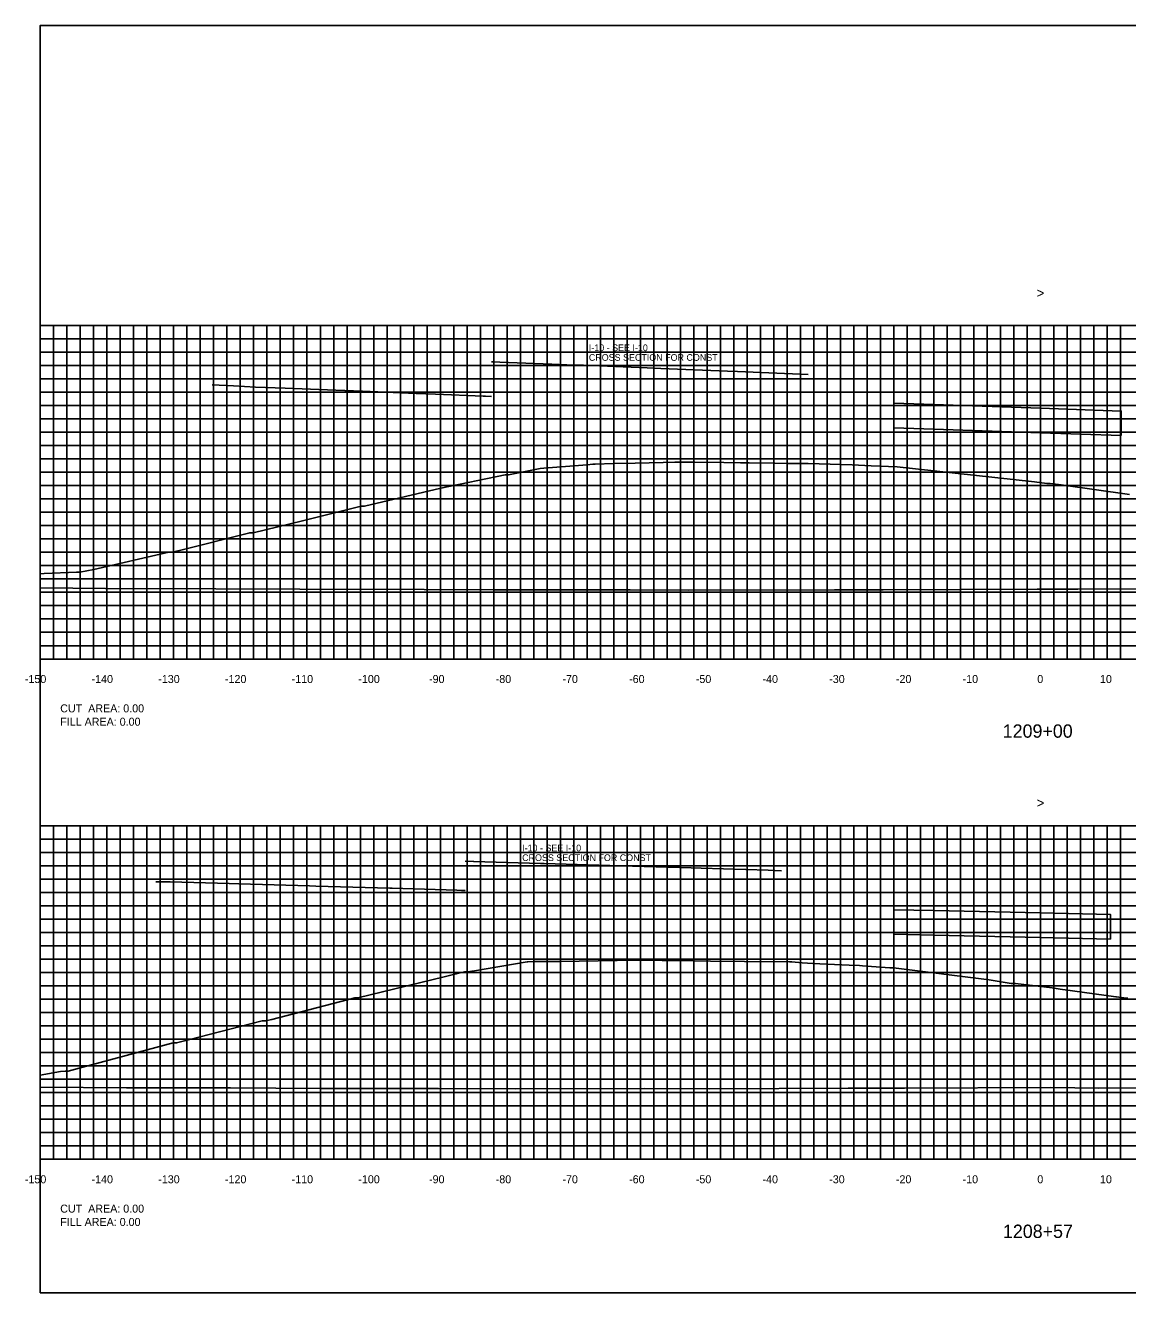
# Model space of a CAD drawing. Extents: x 1797305 to 1804485, y 245831 to 250849.
# Drawn here: x 1803498.8 to 1803664, y 250079.4 to 250269.4 of the extents above; entities that cross this region are included whole.
import ezdxf

# ---------------------------------------------------------------- set-up
doc = ezdxf.new("R2010")
doc.units = 0
for name, color, linetype in [('1', 7, 'Continuous'), ('10', 7, 'Continuous'), ('29', 7, 'Continuous'), ('CL-CNST', 7, 'Continuous'), ('EDPV-LINE', 7, 'Continuous'), ('Level 31', 7, 'Continuous'), ('LIMT-CSLINE', 7, 'Continuous'), ('M-ROADS', 7, 'Continuous'), ('SURVEY - DRAINAGE - Area Shapes', 7, 'Continuous')]:
    doc.layers.add(name, color=color, linetype=linetype)

msp = doc.modelspace()

# ---------------------------------------------------------------- linework, layer by layer
msp.add_lwpolyline([(1803501, 250079.43), (1803801, 250079.43), (1803801, 250269.43), (1803501, 250269.43)], close=True)
at = {"layer": '29'}
for p, q in [((1803501, 250224.43), (1803801, 250224.43)), ((1803501, 250174.43), (1803501, 250224.43)), ((1803503, 250174.43), (1803503, 250224.43)), ((1803505, 250174.43), (1803505, 250224.43)), ((1803507, 250174.43), (1803507, 250224.43)), ((1803509, 250174.43), (1803509, 250224.43)), ((1803511, 250174.43), (1803511, 250224.43)), ((1803513, 250174.43), (1803513, 250224.43)), ((1803515, 250174.43), (1803515, 250224.43)), ((1803517, 250174.43), (1803517, 250224.43)), ((1803519, 250174.43), (1803519, 250224.43)), ((1803521, 250174.43), (1803521, 250224.43)), ((1803523, 250174.43), (1803523, 250224.43)), ((1803525, 250174.43), (1803525, 250224.43)), ((1803527, 250174.43), (1803527, 250224.43)), ((1803529, 250174.43), (1803529, 250224.43)), ((1803531, 250174.43), (1803531, 250224.43)), ((1803533, 250174.43), (1803533, 250224.43)), ((1803535, 250174.43), (1803535, 250224.43)), ((1803537, 250174.43), (1803537, 250224.43)), ((1803539, 250174.43), (1803539, 250224.43)), ((1803541, 250174.43), (1803541, 250224.43)), ((1803543, 250174.43), (1803543, 250224.43)), ((1803545, 250174.43), (1803545, 250224.43)), ((1803547, 250174.43), (1803547, 250224.43)), ((1803549, 250174.43), (1803549, 250224.43)), ((1803551, 250174.43), (1803551, 250224.43)), ((1803553, 250174.43), (1803553, 250224.43)), ((1803555, 250174.43), (1803555, 250224.43)), ((1803557, 250174.43), (1803557, 250224.43)), ((1803559, 250174.43), (1803559, 250224.43)), ((1803561, 250174.43), (1803561, 250224.43)), ((1803563, 250174.43), (1803563, 250224.43)), ((1803565, 250174.43), (1803565, 250224.43)), ((1803567, 250174.43), (1803567, 250224.43)), ((1803569, 250174.43), (1803569, 250224.43)), ((1803571, 250174.43), (1803571, 250224.43)), ((1803573, 250174.43), (1803573, 250224.43)), ((1803575, 250174.43), (1803575, 250224.43)), ((1803577, 250174.43), (1803577, 250224.43)), ((1803579, 250174.43), (1803579, 250224.43)), ((1803581, 250174.43), (1803581, 250224.43)), ((1803583, 250174.43), (1803583, 250224.43)), ((1803585, 250174.43), (1803585, 250224.43)), ((1803587, 250174.43), (1803587, 250224.43)), ((1803589, 250174.43), (1803589, 250224.43)), ((1803591, 250174.43), (1803591, 250224.43)), ((1803593, 250174.43), (1803593, 250224.43)), ((1803595, 250174.43), (1803595, 250224.43)), ((1803597, 250174.43), (1803597, 250224.43)), ((1803599, 250174.43), (1803599, 250224.43)), ((1803601, 250174.43), (1803601, 250224.43)), ((1803603, 250174.43), (1803603, 250224.43)), ((1803605, 250174.43), (1803605, 250224.43)), ((1803607, 250174.43), (1803607, 250224.43)), ((1803609, 250174.43), (1803609, 250224.43)), ((1803611, 250174.43), (1803611, 250224.43)), ((1803613, 250174.43), (1803613, 250224.43)), ((1803615, 250174.43), (1803615, 250224.43)), ((1803617, 250174.43), (1803617, 250224.43)), ((1803619, 250174.43), (1803619, 250224.43)), ((1803621, 250174.43), (1803621, 250224.43)), ((1803623, 250174.43), (1803623, 250224.43)), ((1803625, 250174.43), (1803625, 250224.43)), ((1803627, 250174.43), (1803627, 250224.43)), ((1803629, 250174.43), (1803629, 250224.43)), ((1803631, 250174.43), (1803631, 250224.43)), ((1803633, 250174.43), (1803633, 250224.43)), ((1803635, 250174.43), (1803635, 250224.43)), ((1803637, 250174.43), (1803637, 250224.43)), ((1803639, 250174.43), (1803639, 250224.43)), ((1803641, 250174.43), (1803641, 250224.43)), ((1803643, 250174.43), (1803643, 250224.43)), ((1803645, 250174.43), (1803645, 250224.43)), ((1803647, 250174.43), (1803647, 250224.43)), ((1803649, 250174.43), (1803649, 250224.43)), ((1803651, 250174.43), (1803651, 250224.43)), ((1803653, 250174.43), (1803653, 250224.43)), ((1803655, 250174.43), (1803655, 250224.43)), ((1803657, 250174.43), (1803657, 250224.43)), ((1803659, 250174.43), (1803659, 250224.43)), ((1803661, 250174.43), (1803661, 250224.43)), ((1803663, 250174.43), (1803663, 250224.43)), ((1803501, 250222.43), (1803801, 250222.43)), ((1803501, 250220.43), (1803801, 250220.43)), ((1803501, 250218.43), (1803801, 250218.43)), ((1803501, 250216.43), (1803801, 250216.43)), ((1803501, 250214.43), (1803801, 250214.43)), ((1803501, 250212.43), (1803801, 250212.43)), ((1803501, 250210.43), (1803801, 250210.43)), ((1803501, 250208.43), (1803801, 250208.43)), ((1803501, 250206.43), (1803801, 250206.43)), ((1803501, 250204.43), (1803801, 250204.43)), ((1803501, 250202.43), (1803801, 250202.43)), ((1803501, 250200.43), (1803801, 250200.43)), ((1803501, 250198.43), (1803801, 250198.43)), ((1803501, 250196.43), (1803801, 250196.43)), ((1803501, 250194.43), (1803801, 250194.43)), ((1803501, 250192.43), (1803801, 250192.43)), ((1803501, 250190.43), (1803801, 250190.43)), ((1803501, 250188.43), (1803801, 250188.43)), ((1803501, 250186.43), (1803801, 250186.43)), ((1803501, 250184.43), (1803801, 250184.43)), ((1803501, 250182.43), (1803801, 250182.43)), ((1803501, 250180.43), (1803801, 250180.43)), ((1803501, 250178.43), (1803801, 250178.43)), ((1803501, 250176.43), (1803801, 250176.43)), ((1803501, 250174.43), (1803801, 250174.43)), ((1803501, 250149.43), (1803801, 250149.43)), ((1803501, 250099.43), (1803501, 250149.43)), ((1803503, 250099.43), (1803503, 250149.43)), ((1803505, 250099.43), (1803505, 250149.43)), ((1803507, 250099.43), (1803507, 250149.43)), ((1803509, 250099.43), (1803509, 250149.43)), ((1803511, 250099.43), (1803511, 250149.43)), ((1803513, 250099.43), (1803513, 250149.43)), ((1803515, 250099.43), (1803515, 250149.43)), ((1803517, 250099.43), (1803517, 250149.43)), ((1803519, 250099.43), (1803519, 250149.43)), ((1803521, 250099.43), (1803521, 250149.43)), ((1803523, 250099.43), (1803523, 250149.43)), ((1803525, 250099.43), (1803525, 250149.43)), ((1803527, 250099.43), (1803527, 250149.43)), ((1803529, 250099.43), (1803529, 250149.43)), ((1803531, 250099.43), (1803531, 250149.43)), ((1803533, 250099.43), (1803533, 250149.43)), ((1803535, 250099.43), (1803535, 250149.43)), ((1803537, 250099.43), (1803537, 250149.43)), ((1803539, 250099.43), (1803539, 250149.43)), ((1803541, 250099.43), (1803541, 250149.43)), ((1803543, 250099.43), (1803543, 250149.43)), ((1803545, 250099.43), (1803545, 250149.43)), ((1803547, 250099.43), (1803547, 250149.43)), ((1803549, 250099.43), (1803549, 250149.43)), ((1803551, 250099.43), (1803551, 250149.43)), ((1803553, 250099.43), (1803553, 250149.43)), ((1803555, 250099.43), (1803555, 250149.43)), ((1803557, 250099.43), (1803557, 250149.43)), ((1803559, 250099.43), (1803559, 250149.43)), ((1803561, 250099.43), (1803561, 250149.43)), ((1803563, 250099.43), (1803563, 250149.43)), ((1803565, 250099.43), (1803565, 250149.43)), ((1803567, 250099.43), (1803567, 250149.43)), ((1803569, 250099.43), (1803569, 250149.43)), ((1803571, 250099.43), (1803571, 250149.43)), ((1803573, 250099.43), (1803573, 250149.43)), ((1803575, 250099.43), (1803575, 250149.43)), ((1803577, 250099.43), (1803577, 250149.43)), ((1803579, 250099.43), (1803579, 250149.43)), ((1803581, 250099.43), (1803581, 250149.43)), ((1803583, 250099.43), (1803583, 250149.43)), ((1803585, 250099.43), (1803585, 250149.43)), ((1803587, 250099.43), (1803587, 250149.43)), ((1803589, 250099.43), (1803589, 250149.43)), ((1803591, 250099.43), (1803591, 250149.43)), ((1803593, 250099.43), (1803593, 250149.43)), ((1803595, 250099.43), (1803595, 250149.43)), ((1803597, 250099.43), (1803597, 250149.43)), ((1803599, 250099.43), (1803599, 250149.43)), ((1803601, 250099.43), (1803601, 250149.43)), ((1803603, 250099.43), (1803603, 250149.43)), ((1803605, 250099.43), (1803605, 250149.43)), ((1803607, 250099.43), (1803607, 250149.43)), ((1803609, 250099.43), (1803609, 250149.43)), ((1803611, 250099.43), (1803611, 250149.43)), ((1803613, 250099.43), (1803613, 250149.43)), ((1803615, 250099.43), (1803615, 250149.43)), ((1803617, 250099.43), (1803617, 250149.43)), ((1803619, 250099.43), (1803619, 250149.43)), ((1803621, 250099.43), (1803621, 250149.43)), ((1803623, 250099.43), (1803623, 250149.43)), ((1803625, 250099.43), (1803625, 250149.43)), ((1803627, 250099.43), (1803627, 250149.43)), ((1803629, 250099.43), (1803629, 250149.43)), ((1803631, 250099.43), (1803631, 250149.43)), ((1803633, 250099.43), (1803633, 250149.43)), ((1803635, 250099.43), (1803635, 250149.43)), ((1803637, 250099.43), (1803637, 250149.43)), ((1803639, 250099.43), (1803639, 250149.43)), ((1803641, 250099.43), (1803641, 250149.43)), ((1803643, 250099.43), (1803643, 250149.43)), ((1803645, 250099.43), (1803645, 250149.43)), ((1803647, 250099.43), (1803647, 250149.43)), ((1803649, 250099.43), (1803649, 250149.43)), ((1803651, 250099.43), (1803651, 250149.43)), ((1803653, 250099.43), (1803653, 250149.43)), ((1803655, 250099.43), (1803655, 250149.43)), ((1803657, 250099.43), (1803657, 250149.43)), ((1803659, 250099.43), (1803659, 250149.43)), ((1803661, 250099.43), (1803661, 250149.43)), ((1803663, 250099.43), (1803663, 250149.43)), ((1803501, 250147.43), (1803801, 250147.43)), ((1803501, 250145.43), (1803801, 250145.43)), ((1803501, 250143.43), (1803801, 250143.43)), ((1803501, 250141.43), (1803801, 250141.43)), ((1803501, 250139.43), (1803801, 250139.43)), ((1803501, 250137.43), (1803801, 250137.43)), ((1803501, 250135.43), (1803801, 250135.43)), ((1803501, 250133.43), (1803801, 250133.43)), ((1803501, 250131.43), (1803801, 250131.43)), ((1803501, 250129.43), (1803801, 250129.43)), ((1803501, 250127.43), (1803801, 250127.43)), ((1803501, 250125.43), (1803801, 250125.43)), ((1803501, 250123.43), (1803801, 250123.43)), ((1803501, 250121.43), (1803801, 250121.43)), ((1803501, 250119.43), (1803801, 250119.43)), ((1803501, 250117.43), (1803801, 250117.43)), ((1803501, 250115.43), (1803801, 250115.43)), ((1803501, 250113.43), (1803801, 250113.43)), ((1803501, 250111.43), (1803801, 250111.43)), ((1803501, 250109.43), (1803801, 250109.43)), ((1803501, 250107.43), (1803801, 250107.43)), ((1803501, 250105.43), (1803801, 250105.43)), ((1803501, 250103.43), (1803801, 250103.43)), ((1803501, 250101.43), (1803801, 250101.43)), ((1803501, 250099.43), (1803801, 250099.43))]:
    msp.add_line(p, q, dxfattribs=at)
at = {"layer": 'CL-CNST'}
for points in [[(1803568.67, 250219), (1803568.99, 250218.99), (1803569.93, 250218.95), (1803577.69, 250218.63), (1803579.97, 250218.55), (1803582.48, 250218.46), (1803592.02, 250218.07), (1803594.03, 250217.99), (1803604.07, 250217.57), (1803605.57, 250217.52), (1803616.12, 250217.08)], [(1803526.77, 250215.52), (1803530, 250215.39), (1803533.27, 250215.21), (1803537.75, 250215.05), (1803545.32, 250214.73), (1803549.3, 250214.59), (1803557.37, 250214.24), (1803560.28, 250214.14), (1803567.41, 250213.83), (1803567.74, 250213.82), (1803568.67, 250213.78)], [(1803629, 250212.79), (1803635, 250212.58), (1803651, 250212.03), (1803663.1, 250211.61)], [(1803501, 250185.09), (1803510.77, 250185), (1803527.31, 250184.97), (1803539.92, 250184.88), (1803558.56, 250184.87), (1803569.08, 250184.79), (1803589.45, 250184.81), (1803598.24, 250184.75), (1803620.07, 250184.81), (1803627.4, 250184.78), (1803650.47, 250184.88), (1803656.56, 250184.88), (1803680.69, 250185), (1803685.72, 250184.91), (1803710.78, 250185.05), (1803714.88, 250185.09), (1803718.62, 250185.06), (1803744.03, 250185.2), (1803747.27, 250185.25), (1803773.19, 250185.39), (1803775.9, 250185.32), (1803801, 250185.47)], [(1803564.71, 250144.11), (1803565.95, 250144.07), (1803565.96, 250144.07), (1803566.03, 250144.07), (1803576, 250143.78), (1803576.55, 250143.76), (1803588.05, 250143.42), (1803598.59, 250143.11), (1803600.1, 250143.05), (1803610.14, 250142.75), (1803612.16, 250142.68)], [(1803518.36, 250141.03), (1803520.46, 250141.01), (1803529.31, 250140.77), (1803530.78, 250140.74), (1803541.36, 250140.42), (1803542.32, 250140.39), (1803553.41, 250140.06), (1803553.79, 250140.05), (1803563.45, 250139.75), (1803563.46, 250139.75), (1803564.17, 250139.73), (1803564.7, 250139.71), (1803564.7, 250139.71)], [(1803629, 250136.85), (1803635, 250136.72), (1803651, 250136.37), (1803661.47, 250136.13)], [(1803501, 250110.24), (1803513.94, 250110.15), (1803529.55, 250110.14), (1803543.1, 250110.05), (1803560.71, 250110.06), (1803572.25, 250109.98), (1803591.54, 250110.03), (1803601.41, 250110), (1803622.13, 250110.08), (1803630.57, 250110.09), (1803652.52, 250110.19), (1803659.73, 250110.07), (1803682.75, 250110.19), (1803688.89, 250110.26), (1803694.5, 250110.22), (1803718.05, 250110.35), (1803723.18, 250110.43), (1803747.21, 250110.56), (1803751.83, 250110.43), (1803776.36, 250110.58), (1803782.45, 250110.38), (1803801, 250110.51)]]:
    msp.add_lwpolyline(points, dxfattribs=at)
at = {"layer": 'Level 31'}
for p, q in [((1803500.94, 250224.43), (1803501, 250224.43)), ((1803501, 250174.43), (1803501, 250224.43)), ((1803500.94, 250214.43), (1803501, 250214.43)), ((1803500.94, 250204.43), (1803501, 250204.43)), ((1803500.94, 250194.43), (1803501, 250194.43)), ((1803500.94, 250184.43), (1803501, 250184.43)), ((1803500.94, 250174.43), (1803501, 250174.43)), ((1803501, 250174.43), (1803801, 250174.43)), ((1803501, 250174.37), (1803501, 250174.43)), ((1803511, 250174.37), (1803511, 250174.43)), ((1803521, 250174.37), (1803521, 250174.43)), ((1803531, 250174.37), (1803531, 250174.43)), ((1803541, 250174.37), (1803541, 250174.43)), ((1803551, 250174.37), (1803551, 250174.43)), ((1803561, 250174.37), (1803561, 250174.43)), ((1803571, 250174.37), (1803571, 250174.43)), ((1803581, 250174.37), (1803581, 250174.43)), ((1803591, 250174.37), (1803591, 250174.43)), ((1803601, 250174.37), (1803601, 250174.43)), ((1803611, 250174.37), (1803611, 250174.43)), ((1803621, 250174.37), (1803621, 250174.43)), ((1803631, 250174.37), (1803631, 250174.43)), ((1803641, 250174.37), (1803641, 250174.43)), ((1803651, 250174.37), (1803651, 250174.43)), ((1803661, 250174.37), (1803661, 250174.43)), ((1803500.94, 250149.43), (1803501, 250149.43)), ((1803501, 250099.43), (1803501, 250149.43)), ((1803500.94, 250139.43), (1803501, 250139.43)), ((1803500.94, 250129.43), (1803501, 250129.43)), ((1803500.94, 250119.43), (1803501, 250119.43)), ((1803500.94, 250109.43), (1803501, 250109.43)), ((1803500.94, 250099.43), (1803501, 250099.43)), ((1803501, 250099.43), (1803801, 250099.43)), ((1803501, 250099.37), (1803501, 250099.43)), ((1803511, 250099.37), (1803511, 250099.43)), ((1803521, 250099.37), (1803521, 250099.43)), ((1803531, 250099.37), (1803531, 250099.43)), ((1803541, 250099.37), (1803541, 250099.43)), ((1803551, 250099.37), (1803551, 250099.43)), ((1803561, 250099.37), (1803561, 250099.43)), ((1803571, 250099.37), (1803571, 250099.43)), ((1803581, 250099.37), (1803581, 250099.43)), ((1803591, 250099.37), (1803591, 250099.43)), ((1803601, 250099.37), (1803601, 250099.43)), ((1803611, 250099.37), (1803611, 250099.43)), ((1803621, 250099.37), (1803621, 250099.43)), ((1803631, 250099.37), (1803631, 250099.43)), ((1803641, 250099.37), (1803641, 250099.43)), ((1803651, 250099.37), (1803651, 250099.43)), ((1803661, 250099.37), (1803661, 250099.43))]:
    msp.add_line(p, q, dxfattribs=at)
at = {"layer": 'M-ROADS'}
for points in [[(1803501, 250187.22), (1803501.58, 250187.26), (1803506.46, 250187.44), (1803506.86, 250187.44), (1803506.93, 250187.45), (1803509.03, 250187.87), (1803520.28, 250190.43), (1803520.29, 250190.43), (1803520.78, 250190.43), (1803521.61, 250190.64), (1803521.66, 250190.66), (1803532.41, 250193.37), (1803532.64, 250193.37), (1803532.92, 250193.37), (1803540.35, 250195.17), (1803549.11, 250197.35), (1803549.4, 250197.35), (1803549.63, 250197.35), (1803561.05, 250200.04), (1803570.7, 250202.02), (1803570.91, 250202.02), (1803571.21, 250202.02), (1803575.96, 250202.98), (1803576.52, 250203.06), (1803583, 250203.56), (1803583.88, 250203.65), (1803584.19, 250203.66), (1803586.97, 250203.73), (1803590.22, 250203.81), (1803594.38, 250203.91), (1803596.16, 250203.96), (1803599.16, 250203.93), (1803603.49, 250203.89), (1803605.99, 250203.86), (1803607.29, 250203.85), (1803611.14, 250203.79), (1803612.96, 250203.76), (1803613.41, 250203.76), (1803614.68, 250203.75), (1803615.5, 250203.74), (1803615.65, 250203.74), (1803616.16, 250203.72), (1803622.76, 250203.56), (1803625.59, 250203.39), (1803629.5, 250203.24), (1803650.06, 250200.97), (1803651.93, 250200.75), (1803651.99, 250200.75), (1803652.44, 250200.75), (1803654.08, 250200.52), (1803664.32, 250199.09)], [(1803501, 250112.04), (1803504.05, 250112.57), (1803504.75, 250112.63), (1803505.18, 250112.63), (1803507.39, 250113.23), (1803520.93, 250116.87), (1803520.99, 250116.87), (1803521.45, 250116.87), (1803523.24, 250117.34), (1803534.28, 250120.17), (1803534.3, 250120.17), (1803534.78, 250120.17), (1803535.74, 250120.4), (1803548.15, 250123.61), (1803548.51, 250123.61), (1803548.64, 250123.61), (1803561.57, 250126.79), (1803563.39, 250127.22), (1803564.61, 250127.51), (1803564.62, 250127.51), (1803565.09, 250127.51), (1803565.73, 250127.61), (1803565.84, 250127.62), (1803574, 250129.01), (1803574.11, 250129.01), (1803574.95, 250129.06), (1803575.02, 250129.06), (1803575.51, 250129.06), (1803575.7, 250129.06), (1803578.56, 250129.06), (1803578.94, 250129.06), (1803578.96, 250129.07), (1803590.34, 250129.3), (1803591.69, 250129.28), (1803594.25, 250129.25), (1803599.02, 250129.19), (1803601.52, 250129.15), (1803606.6, 250129.1), (1803613.33, 250129.03), (1803613.33, 250129.03), (1803613.69, 250129.01), (1803615.24, 250128.9), (1803616.86, 250128.79), (1803617.87, 250128.74), (1803622.28, 250128.53), (1803623.85, 250128.46), (1803624.31, 250128.43), (1803628.41, 250128.15), (1803628.83, 250128.15), (1803628.92, 250128.15), (1803643.26, 250126.33), (1803646.57, 250125.79), (1803646.66, 250125.78), (1803647.07, 250125.78), (1803647.23, 250125.76), (1803652.73, 250125.11), (1803653.93, 250124.94), (1803655.78, 250124.69), (1803659.02, 250124.24), (1803662.3, 250123.77), (1803662.37, 250123.76), (1803663.47, 250123.62), (1803663.89, 250123.58), (1803664, 250123.56), (1803664.08, 250123.56)]]:
    msp.add_lwpolyline(points, dxfattribs=at)
at = {"layer": 'SURVEY - DRAINAGE - Area Shapes'}
for points in [[(1803663.1, 250207.93), (1803663.1, 250211.61), (1803651, 250212.03), (1803635, 250212.58), (1803629, 250212.79), (1803629, 250209.11), (1803635, 250208.9), (1803651, 250208.35)], [(1803661.47, 250132.45), (1803661.47, 250136.13), (1803651, 250136.37), (1803635, 250136.72), (1803629, 250136.85), (1803629, 250133.17), (1803635, 250133.04), (1803651, 250132.69)]]:
    msp.add_lwpolyline(points, close=True, dxfattribs=at)

# ---------------------------------------------------------------- texts
at = {"layer": '1'}
for s, p in [('1209+00', (1803645.32, 250162.63)), ('1208+57', (1803645.35, 250087.63))]:
    msp.add_text(s, height=2, dxfattribs=at).set_placement(p)
at = {"layer": '10'}
for s, p in [('-150', (1803498.7, 250170.83)), ('-140', (1803508.7, 250170.83)), ('-130', (1803518.7, 250170.83)), ('-120', (1803528.7, 250170.83)), ('-110', (1803538.7, 250170.83)), ('-100', (1803548.7, 250170.83)), ('-90', (1803559.3, 250170.83)), ('-80', (1803569.3, 250170.83)), ('-70', (1803579.3, 250170.83)), ('-60', (1803589.3, 250170.83)), ('-50', (1803599.3, 250170.83)), ('-40', (1803609.3, 250170.83)), ('-30', (1803619.3, 250170.83)), ('-20', (1803629.3, 250170.83)), ('-10', (1803639.3, 250170.83)), ('0', (1803650.5, 250170.83)), ('10', (1803659.9, 250170.83)), ('-150', (1803498.7, 250095.83)), ('-140', (1803508.7, 250095.83)), ('-130', (1803518.7, 250095.83)), ('-120', (1803528.7, 250095.83)), ('-110', (1803538.7, 250095.83)), ('-100', (1803548.7, 250095.83)), ('-90', (1803559.3, 250095.83)), ('-80', (1803569.3, 250095.83)), ('-70', (1803579.3, 250095.83)), ('-60', (1803589.3, 250095.83)), ('-50', (1803599.3, 250095.83)), ('-40', (1803609.3, 250095.83)), ('-30', (1803619.3, 250095.83)), ('-20', (1803629.3, 250095.83)), ('-10', (1803639.3, 250095.83)), ('0', (1803650.5, 250095.83)), ('10', (1803659.9, 250095.83))]:
    msp.add_text(s, height=1.2, dxfattribs=at).set_placement(p)
at = {"layer": 'EDPV-LINE'}
for s, p in [('CUT  AREA: 0.00', (1803504, 250166.43)), ('FILL AREA: 0.00', (1803504, 250164.43)), ('CUT  AREA: 0.00', (1803504, 250091.43)), ('FILL AREA: 0.00', (1803504, 250089.43))]:
    msp.add_text(s, height=1.2, dxfattribs=at).set_placement(p)
at = {"layer": 'Level 31'}
for s, height, p in [('>', 1.5, (1803650.39, 250228.56)), ('-', 0.0001, (1803501, 250174.43)), ('>', 1.5, (1803650.39, 250152.12)), ('-', 0.0001, (1803501, 250099.43))]:
    msp.add_text(s, height=height, dxfattribs=at).set_placement(p)
at = {"layer": 'LIMT-CSLINE'}
for s, p in [('I-10 - SEE I-10', (1803583.26, 250220.59)), ('CROSS SECTION FOR CONST ', (1803583.26, 250219.14)), ('I-10 - SEE I-10', (1803573.26, 250145.59)), ('CROSS SECTION FOR CONST ', (1803573.26, 250144.14))]:
    msp.add_text(s, height=1, dxfattribs=at).set_placement(p)

doc.saveas('drawing.dxf')
